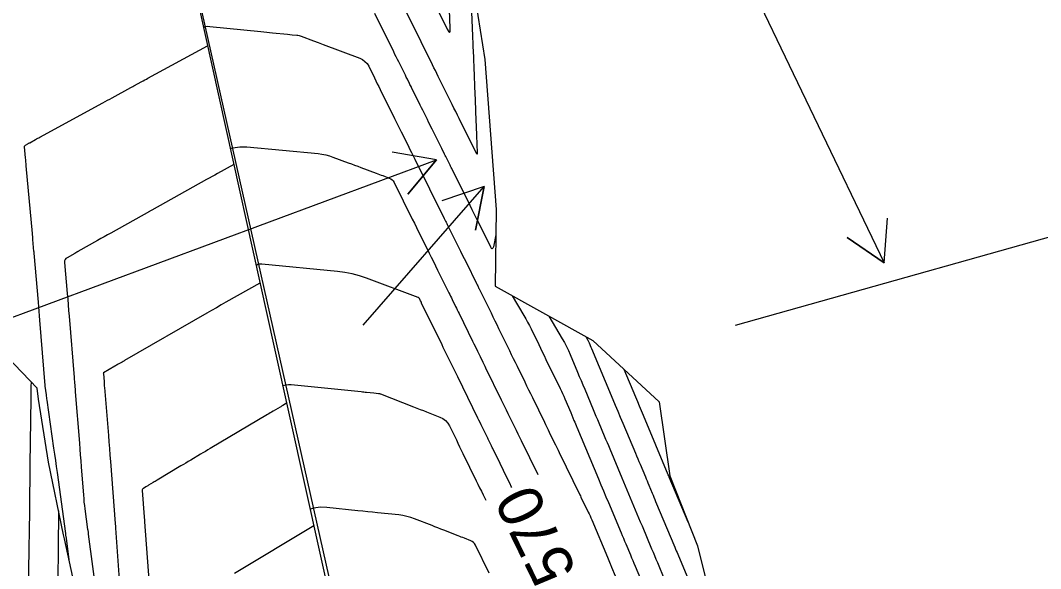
# Model space of a CAD drawing. Extents: x 954385 to 988206, y 1868364 to 1924553.
# Drawn here: x 957911.1 to 958048.1, y 1919236.3 to 1919309.9 of the extents above; entities that cross this region are included whole.
import ezdxf

# ---------------------------------------------------------------- set-up
doc = ezdxf.new("R2010")
doc.units = 0
for name, color, linetype in [('13', 7, 'Continuous'), ('22', 7, 'Continuous'), ('23', 7, 'Continuous'), ('24', 7, 'Continuous'), ('26', 7, 'Continuous'), ('5', 7, 'Continuous'), ('6', 7, 'Continuous'), ('7', 7, 'Continuous'), ('Default', 7, 'Continuous')]:
    doc.layers.add(name, color=color, linetype=linetype)

msp = doc.modelspace()

# ---------------------------------------------------------------- linework, layer by layer
at = {"layer": '13'}
for points in [[(957917.69, 1919237.11), (957917.27, 1919240.31), (957917.26, 1919240.36), (957917.21, 1919240.72), (957917.2, 1919240.78), (957917.2, 1919240.84), (957917.19, 1919240.91), (957917.18, 1919240.97), (957916.06, 1919249.16), (957915.94, 1919249.97), (957915.83, 1919250.78), (957915.72, 1919251.6), (957915.6, 1919252.41), (957914.69, 1919258.86), (957914.66, 1919259.05), (957914.64, 1919259.23), (957914.61, 1919259.42), (957914.58, 1919259.61), (957914.42, 1919260.74), (957914.41, 1919260.8), (957914.41, 1919260.81), (957914.41, 1919260.82), (957914.41, 1919260.83), (957914.41, 1919260.84), (957913.7, 1919269.6), (957913.65, 1919270.2), (957913.6, 1919270.81), (957913.55, 1919271.41), (957913.5, 1919272.02), (957912.93, 1919278.64), (957912.93, 1919278.69), (957912.92, 1919278.75), (957912.92, 1919278.8), (957912.91, 1919278.85), (957912.77, 1919280.44), (957912.75, 1919280.65), (957912.74, 1919280.86), (957912.72, 1919281.07), (957912.7, 1919281.28), (957911.88, 1919290.36), (957911.86, 1919290.63), (957911.83, 1919290.9), (957911.81, 1919291.17), (957911.79, 1919291.44), (957911.66, 1919292.91), (957911.66, 1919292.99), (957911.68, 1919293.05), (957911.72, 1919293.11), (957911.78, 1919293.15), (957912.07, 1919293.31), (957912.14, 1919293.35), (957912.21, 1919293.38), (957912.28, 1919293.42), (957912.35, 1919293.46), (957913.11, 1919293.88), (957913.26, 1919293.96), (957913.41, 1919294.05), (957913.56, 1919294.13), (957913.71, 1919294.21), (957922.16, 1919298.81), (957922.48, 1919298.99), (957922.79, 1919299.16), (957923.11, 1919299.33), (957923.42, 1919299.5), (957925.9, 1919300.87), (957926, 1919300.92), (957926.1, 1919300.97), (957926.2, 1919301.03), (957926.3, 1919301.08), (957927.38, 1919301.66), (957927.59, 1919301.77), (957927.8, 1919301.89), (957928.01, 1919302), (957928.22, 1919302.12), (957936.23, 1919306.49)], [(957939.75, 1919290.51), (957937.56, 1919289.31), (957937.19, 1919289.11), (957936.82, 1919288.91), (957936.46, 1919288.71), (957936.09, 1919288.51), (957928.72, 1919284.39), (957928.67, 1919284.37), (957928.49, 1919284.27), (957928.41, 1919284.22), (957923.25, 1919281.33), (957922.8, 1919281.08), (957922.35, 1919280.83), (957921.9, 1919280.57), (957921.45, 1919280.32), (957918.81, 1919278.84), (957918.78, 1919278.82), (957918.74, 1919278.8), (957918.71, 1919278.78), (957918.67, 1919278.75), (957918.52, 1919278.67), (957918.49, 1919278.65), (957918.45, 1919278.63), (957918.42, 1919278.61), (957918.38, 1919278.59), (957917.35, 1919278.01), (957917.19, 1919277.89), (957917.08, 1919277.75), (957917.03, 1919277.58), (957917.02, 1919277.38), (957917.38, 1919273.2), (957917.44, 1919272.44), (957917.51, 1919271.67), (957917.57, 1919270.9), (957917.63, 1919270.14), (957918.3, 1919261.93), (957918.31, 1919261.77), (957918.32, 1919261.61), (957918.34, 1919261.45), (957918.35, 1919261.29), (957918.43, 1919260.27), (957918.44, 1919260.14), (957918.44, 1919260.08), (957918.45, 1919260.01), (957919.01, 1919253.1), (957919.07, 1919252.31), (957919.13, 1919251.52), (957919.19, 1919250.73), (957919.25, 1919249.94), (957919.55, 1919246.12), (957919.59, 1919245.66), (957919.63, 1919245.19), (957919.68, 1919244.73), (957919.74, 1919244.27), (957920.12, 1919241.52), (957920.13, 1919241.47), (957920.18, 1919241.07), (957920.19, 1919241.02), (957920.2, 1919240.97), (957920.2, 1919240.91), (957920.21, 1919240.86), (957921.26, 1919232.87)], [(957943.26, 1919274.6), (957938.68, 1919272.02), (957938.04, 1919271.66), (957937.41, 1919271.3), (957936.77, 1919270.93), (957936.13, 1919270.57), (957925.09, 1919264.2), (957924.98, 1919264.13), (957924.87, 1919264.07), (957924.76, 1919264), (957924.65, 1919263.94), (957924.2, 1919263.69), (957924.09, 1919263.62), (957923.98, 1919263.56), (957923.87, 1919263.49), (957923.76, 1919263.43), (957922.24, 1919262.55), (957922.23, 1919262.54), (957922.23, 1919262.54), (957922.22, 1919262.54), (957922.23, 1919262.46), (957922.32, 1919261.32), (957922.33, 1919261.13), (957922.35, 1919260.94), (957922.36, 1919260.76), (957922.38, 1919260.57), (957922.9, 1919254.15), (957922.97, 1919253.26), (957923.04, 1919252.38), (957923.11, 1919251.5), (957923.17, 1919250.62), (957923.81, 1919242.33), (957923.81, 1919242.29), (957923.84, 1919241.89), (957923.85, 1919241.83), (957923.85, 1919241.77), (957923.85, 1919241.72), (957923.86, 1919241.66), (957924.48, 1919232.92)], [(957946.83, 1919258.46), (957946.31, 1919258.16), (957946.22, 1919258.11), (957946.14, 1919258.06), (957946.05, 1919258), (957945.96, 1919257.95), (957945.02, 1919257.39), (957944.83, 1919257.28), (957944.64, 1919257.17), (957944.46, 1919257.06), (957944.27, 1919256.95), (957936.59, 1919252.39), (957936.26, 1919252.19), (957935.93, 1919252), (957935.6, 1919251.8), (957935.27, 1919251.61), (957933.96, 1919250.82), (957933.63, 1919250.62), (957933.31, 1919250.43), (957932.98, 1919250.23), (957932.65, 1919250.04), (957929.44, 1919248.13), (957929.31, 1919248.05), (957929.18, 1919247.97), (957929.05, 1919247.89), (957928.91, 1919247.81), (957928.3, 1919247.44), (957928.21, 1919247.39), (957928.12, 1919247.34), (957928.04, 1919247.29), (957927.95, 1919247.23), (957927.6, 1919247.03), (957927.53, 1919246.97), (957927.48, 1919246.9), (957927.45, 1919246.82), (957927.44, 1919246.72), (957927.71, 1919243.2), (957927.72, 1919243.15), (957927.75, 1919242.75), (957927.75, 1919242.69), (957927.75, 1919242.64), (957927.76, 1919242.59), (957927.76, 1919242.54), (957928.36, 1919234.15)], [(957939.85, 1919235.64), (957950.47, 1919242.04)]]:
    msp.add_lwpolyline(points, dxfattribs=at)
at = {"layer": '22'}
msp.add_lwpolyline([(957913.34, 1919260.51), (957905.2, 1919268.95), (957901.47, 1919276.22), (957900.45, 1919278.15), (957895.68, 1919287.34), (957892.38, 1919294.08), (957891.08, 1919296.54), (957886.89, 1919305.86), (957884.81, 1919311.67), (957883.53, 1919315.36), (957879.3, 1919324.66), (957877.21, 1919329.27), (957875.44, 1919333.92), (957871.95, 1919343.39), (957870.15, 1919347.96), (957868.24, 1919352.81), (957864.59, 1919362.24), (957862.78, 1919366.71), (957860.74, 1919371.53), (957856.68, 1919380.86), (957854.25, 1919386.89), (957852.72, 1919390.22), (957848.14, 1919399.44)], dxfattribs=at)
at = {"layer": '23'}
msp.add_lwpolyline([(957937.99, 1919144.23), (957936.12, 1919152.9), (957934.67, 1919159.76), (957934.04, 1919162.68), (957931.82, 1919172.43), (957930.09, 1919179.85), (957929.57, 1919182.18), (957927.35, 1919191.93), (957925.3, 1919200.72), (957925.06, 1919201.66), (957922.64, 1919211.37), (957920.8, 1919221.2), (957920.73, 1919221.63), (957919.01, 1919231), (957917.01, 1919240.26), (957916.9, 1919240.78), (957914.86, 1919250.57), (957913.54, 1919258.99), (957913.34, 1919260.51)], dxfattribs=at)
at = {"layer": '24'}
for points in [[(957910.49, 1919421.74), (957920, 1919379.49), (957928.68, 1919340.64), (957936.81, 1919303.87), (957945.16, 1919266), (957953.4, 1919228.82)], [(957950.26, 1919401.91), (957951.58, 1919391.96), (957954.19, 1919382.29), (957956.96, 1919372.67), (957961.23, 1919363.38), (957964.4, 1919353.84), (957966.1, 1919344.99), (957968.06, 1919334.16), (957970.2, 1919324.39), (957971.9, 1919314.53), (957973.45, 1919304.62), (957974.2, 1919294.54), (957974.99, 1919284.47), (957974.82, 1919274.19), (957987.94, 1919266.88), (957996.88, 1919258.64), (957998.3, 1919248.71), (958002.02, 1919239.29), (958004.43, 1919229.59)], [(957919.01, 1919231), (957917.01, 1919240.26), (957916.9, 1919240.78), (957914.86, 1919250.57), (957913.54, 1919258.99), (957913.34, 1919260.51), (957905.2, 1919268.95)]]:
    msp.add_lwpolyline(points, dxfattribs=at)
at = {"layer": '26'}
for points in [[(958007.13, 1919318.93), (958027.06, 1919277.33), (958022.11, 1919280.72), (958027.06, 1919277.33), (958027.52, 1919283.31)], [(957907.13, 1919268.93), (957966.95, 1919291.17), (957963.12, 1919286.54), (957966.95, 1919291.17), (957961.03, 1919292.17)], [(957957.13, 1919268.93), (957973.35, 1919287.59), (957972.2, 1919281.7), (957973.35, 1919287.59), (957967.67, 1919285.64)], [(958007.13, 1919268.93), (958061.22, 1919284.17), (958057.03, 1919279.87), (958061.22, 1919284.17), (958055.41, 1919285.65)]]:
    msp.add_lwpolyline(points, dxfattribs=at)
at = {"layer": '6'}
for points in [[(957966.83, 1919311.87), (957968.4, 1919308.69), (957968.6, 1919308.36), (957968.73, 1919308.26), (957968.8, 1919308.41), (957968.81, 1919308.8), (957968.71, 1919311.35)], [(957977.06, 1919247.16), (957977.01, 1919247.28), (957976.84, 1919247.62), (957976.67, 1919247.97), (957975.96, 1919249.43), (957975.81, 1919249.73), (957975.66, 1919250.04), (957975.51, 1919250.35), (957975.36, 1919250.66), (957974.59, 1919252.25), (957974.52, 1919252.37), (957974.46, 1919252.5), (957974.4, 1919252.62), (957974.34, 1919252.75), (957974.04, 1919253.37), (957973.91, 1919253.62), (957973.85, 1919253.75), (957973.1, 1919255.28), (957972.96, 1919255.58), (957972.81, 1919255.88), (957972.67, 1919256.18), (957972.52, 1919256.47), (957969.82, 1919262.02), (957969.64, 1919262.38), (957969.47, 1919262.74), (957969.29, 1919263.1), (957969.11, 1919263.46), (957968.41, 1919264.89), (957968.23, 1919265.25), (957968.06, 1919265.61), (957967.88, 1919265.97), (957967.71, 1919266.33), (957964.97, 1919271.92), (957964.96, 1919271.95), (957964.95, 1919271.97), (957964.94, 1919272), (957964.93, 1919272.02), (957964.83, 1919272.22), (957964.68, 1919272.52), (957964.65, 1919272.57), (957964.6, 1919272.62), (957964.56, 1919272.65), (957964.5, 1919272.68), (957957.57, 1919275.26), (957956.62, 1919275.59), (957955.64, 1919275.85), (957954.65, 1919276.04), (957953.65, 1919276.17), (957943.49, 1919277.13), (957943.18, 1919277.16), (957943.14, 1919277.16), (957943.11, 1919277.16), (957943.07, 1919277.15), (957943.04, 1919277.13), (957942.78, 1919276.97), (957942.74, 1919276.95)], [(957987, 1919267.41), (957987.28, 1919266.92), (957987.33, 1919266.84), (957987.38, 1919266.75), (957987.42, 1919266.67), (957987.45, 1919266.58), (957987.69, 1919266.01), (957987.77, 1919265.83), (957990.64, 1919258.98), (957990.97, 1919258.19), (957991.31, 1919257.39), (957991.64, 1919256.59), (957991.98, 1919255.79), (957993.67, 1919251.76), (957993.83, 1919251.38), (957993.98, 1919251.01), (957994.14, 1919250.64), (957994.3, 1919250.26), (957995.01, 1919248.57), (957995.12, 1919248.3), (957995.24, 1919248.02), (957995.35, 1919247.75), (957995.47, 1919247.47), (957995.93, 1919246.38), (957996.04, 1919246.1), (957996.16, 1919245.83), (957996.27, 1919245.55), (957996.39, 1919245.28), (957998.97, 1919239.11), (957999.07, 1919238.88), (957999.16, 1919238.65), (957999.26, 1919238.43), (957999.36, 1919238.2), (958000.13, 1919236.37), (958003.01, 1919229.5)], [(957916.22, 1919244.01), (957916.16, 1919238.96), (957916.16, 1919238.7), (957916.15, 1919238.44), (957916.15, 1919238.18), (957916.15, 1919237.92), (957916.09, 1919233.61)]]:
    msp.add_lwpolyline(points, dxfattribs=at)
at = {"layer": '7'}
for points in [[(957971.55, 1919314.29), (957971.81, 1919307.77), (957971.82, 1919307.42), (957971.84, 1919307.07), (957971.85, 1919306.72), (957971.86, 1919306.37), (957971.92, 1919304.98), (957971.93, 1919304.64), (957971.95, 1919304.29), (957971.96, 1919303.94), (957971.98, 1919303.59), (957972.12, 1919299.94), (957972.14, 1919299.36), (957972.16, 1919298.77), (957972.19, 1919298.19), (957972.21, 1919297.61), (957972.33, 1919294.52), (957972.34, 1919294.32), (957972.34, 1919294.13), (957972.35, 1919293.93), (957972.36, 1919293.74), (957972.4, 1919292.76), (957972.41, 1919292.57), (957972.41, 1919292.39), (957972.43, 1919292.01), (957972.43, 1919291.94), (957972.41, 1919291.91), (957972.39, 1919291.93), (957972.35, 1919291.99), (957970.01, 1919296.71), (957969.78, 1919297.18), (957969.54, 1919297.64), (957969.31, 1919298.11), (957969.08, 1919298.57), (957967.2, 1919302.36), (957967.01, 1919302.75), (957966.82, 1919303.14), (957966.62, 1919303.52), (957966.43, 1919303.91), (957965.66, 1919305.47), (957965.28, 1919306.25), (957964.89, 1919307.02), (957962.39, 1919312.08)], [(957974.93, 1919281.09), (957974.6, 1919279.49), (957974.54, 1919279.29), (957974.46, 1919279.21), (957974.36, 1919279.26), (957974.25, 1919279.44), (957972.68, 1919282.6), (957972.38, 1919283.21), (957972.08, 1919283.82), (957971.77, 1919284.43), (957971.47, 1919285.04), (957969.01, 1919289.98), (957968.94, 1919290.14), (957968.86, 1919290.3), (957968.78, 1919290.46), (957968.7, 1919290.62), (957968.38, 1919291.27), (957968.3, 1919291.43), (957968.22, 1919291.59), (957968.14, 1919291.75), (957968.06, 1919291.91), (957967.67, 1919292.68), (957967.49, 1919293.04), (957967.31, 1919293.4), (957966.38, 1919295.28), (957966.22, 1919295.6), (957966.06, 1919295.92), (957965.9, 1919296.24), (957965.74, 1919296.56), (957965.11, 1919297.84), (957964.95, 1919298.16), (957964.79, 1919298.48), (957964.63, 1919298.8), (957964.47, 1919299.12), (957963.61, 1919300.86), (957963.54, 1919301), (957963.47, 1919301.14), (957963.4, 1919301.28), (957963.33, 1919301.42), (957963.05, 1919301.98), (957962.98, 1919302.12), (957962.91, 1919302.26), (957962.84, 1919302.4), (957962.78, 1919302.54), (957961.9, 1919304.31), (957961.73, 1919304.65), (957961.56, 1919304.99), (957961.39, 1919305.33), (957961.23, 1919305.67), (957958.68, 1919310.82)], [(957935.68, 1919308.98), (957935.68, 1919308.98), (957935.95, 1919309.06), (957936.23, 1919309.1), (957936.52, 1919309.09), (957943.39, 1919308.38), (957943.78, 1919308.34), (957944.16, 1919308.3), (957944.55, 1919308.26), (957944.94, 1919308.23), (957946.97, 1919308.03), (957947.28, 1919308), (957947.59, 1919307.97), (957948.21, 1919307.91), (957948.36, 1919307.89), (957948.51, 1919307.86), (957948.66, 1919307.82), (957948.8, 1919307.77), (957950.45, 1919307.15), (957951.09, 1919306.9), (957951.74, 1919306.66), (957956.66, 1919304.8), (957957.04, 1919304.62), (957957.36, 1919304.38), (957957.64, 1919304.08), (957957.86, 1919303.72), (957958.62, 1919302.16), (957958.82, 1919301.77), (957959.01, 1919301.38), (957959.2, 1919301), (957959.4, 1919300.61), (957961.33, 1919296.72), (957961.55, 1919296.26), (957961.78, 1919295.81), (957962.01, 1919295.35), (957962.23, 1919294.9), (957963.14, 1919293.07), (957963.36, 1919292.62), (957963.59, 1919292.16), (957963.82, 1919291.71), (957964.04, 1919291.25), (957968, 1919283.3), (957968.19, 1919282.91), (957968.24, 1919282.8), (957968.35, 1919282.59), (957968.4, 1919282.48), (957969.93, 1919279.41), (957970.18, 1919278.91), (957970.43, 1919278.4), (957970.68, 1919277.9), (957970.93, 1919277.4), (957972.34, 1919274.55), (957972.43, 1919274.38), (957972.51, 1919274.22), (957972.67, 1919273.89), (957972.71, 1919273.81), (957972.76, 1919273.72), (957972.8, 1919273.64), (957972.84, 1919273.56), (957974.29, 1919270.59), (957974.54, 1919270.07), (957974.8, 1919269.54), (957975.05, 1919269.02), (957975.31, 1919268.5), (957976.76, 1919265.54), (957977.01, 1919265.01), (957977.27, 1919264.49), (957977.53, 1919263.96), (957977.78, 1919263.44), (957978.81, 1919261.33), (957979.07, 1919260.81), (957979.32, 1919260.28), (957979.58, 1919259.76), (957979.84, 1919259.23), (957981.45, 1919255.93), (957981.61, 1919255.59), (957981.78, 1919255.25), (957981.95, 1919254.91), (957982.11, 1919254.57), (957982.78, 1919253.2), (957982.94, 1919252.86), (957983.11, 1919252.52), (957983.28, 1919252.18), (957983.44, 1919251.84), (957986.21, 1919246.17), (957986.29, 1919246.01), (957986.36, 1919245.86), (957987.34, 1919243.85), (957987.47, 1919243.59), (957987.59, 1919243.33), (957987.7, 1919243.07), (957987.82, 1919242.8), (957989.92, 1919237.79), (957990.01, 1919237.57), (957990.1, 1919237.35), (957990.29, 1919236.9), (957990.34, 1919236.79), (957990.38, 1919236.68), (957990.43, 1919236.57), (957990.47, 1919236.46), (957993.42, 1919229.47)], [(957939.27, 1919292.68), (957939.6, 1919292.78), (957940.54, 1919292.92), (957941.51, 1919292.9), (957951.07, 1919291.99), (957951.58, 1919291.92), (957952.09, 1919291.83), (957952.58, 1919291.7), (957953.06, 1919291.53), (957955.12, 1919290.76), (957955.54, 1919290.61), (957955.96, 1919290.45), (957956.38, 1919290.29), (957956.8, 1919290.14), (957958.87, 1919289.36), (957959.09, 1919289.28), (957959.3, 1919289.2), (957959.52, 1919289.12), (957959.74, 1919289.04), (957960.61, 1919288.71), (957960.82, 1919288.62), (957960.99, 1919288.49), (957961.14, 1919288.33), (957961.26, 1919288.13), (957963.7, 1919283.21), (957963.99, 1919282.64), (957964.27, 1919282.07), (957964.55, 1919281.5), (957964.84, 1919280.92), (957965.97, 1919278.64), (957966.26, 1919278.07), (957966.54, 1919277.5), (957966.82, 1919276.93), (957967.11, 1919276.36), (957968.62, 1919273.31), (957968.74, 1919273.08), (957968.85, 1919272.85), (957968.96, 1919272.61), (957969.08, 1919272.38), (957969.53, 1919271.45), (957969.65, 1919271.22), (957969.76, 1919270.99), (957969.87, 1919270.76), (957969.99, 1919270.52), (957971.81, 1919266.8), (957971.98, 1919266.46), (957972.14, 1919266.12), (957972.48, 1919265.44), (957972.56, 1919265.27), (957972.64, 1919265.1), (957972.72, 1919264.93), (957972.81, 1919264.76), (957973.19, 1919263.98), (957973.28, 1919263.8), (957973.37, 1919263.61), (957973.46, 1919263.43), (957973.55, 1919263.24), (957975.66, 1919258.92), (957975.88, 1919258.47), (957976.1, 1919258.01), (957976.32, 1919257.56), (957976.54, 1919257.1), (957977.43, 1919255.28), (957977.65, 1919254.83), (957977.88, 1919254.37), (957978.1, 1919253.92), (957978.32, 1919253.47), (957980.56, 1919248.87)], [(957977.14, 1919272.89), (957978.7, 1919270.25), (957978.95, 1919269.8), (957979.2, 1919269.36), (957979.44, 1919268.9), (957979.67, 1919268.44), (957980.69, 1919266.36), (957980.93, 1919265.86), (957981.17, 1919265.36), (957981.42, 1919264.86), (957981.66, 1919264.36), (957983.58, 1919260.44), (957983.74, 1919260.1), (957983.9, 1919259.76), (957984.05, 1919259.42), (957984.2, 1919259.07), (957984.98, 1919257.2), (957985.12, 1919256.87), (957985.42, 1919256.16), (957985.52, 1919255.91), (957985.7, 1919255.49), (957985.77, 1919255.32), (957985.8, 1919255.24), (957988.71, 1919248.3), (957989.05, 1919247.51), (957989.38, 1919246.71), (957989.72, 1919245.91), (957990.05, 1919245.11), (957991.75, 1919241.06), (957991.9, 1919240.69), (957992.06, 1919240.32), (957992.22, 1919239.95), (957992.37, 1919239.57), (957993, 1919238.09), (957993.15, 1919237.71), (957993.31, 1919237.34), (957993.47, 1919236.97), (957993.62, 1919236.6), (957995.46, 1919232.23)], [(957982.07, 1919270.15), (957983.86, 1919267.11), (957984.15, 1919266.6), (957984.42, 1919266.08), (957984.67, 1919265.55), (957984.91, 1919265.02), (957985.9, 1919262.65), (957986.14, 1919262.07), (957986.38, 1919261.5), (957986.62, 1919260.92), (957986.87, 1919260.35), (957988.01, 1919257.61), (957988.2, 1919257.17), (957988.38, 1919256.73), (957988.57, 1919256.29), (957988.75, 1919255.85), (957989.49, 1919254.09), (957989.67, 1919253.65), (957989.86, 1919253.21), (957990.04, 1919252.77), (957990.23, 1919252.33), (957991.86, 1919248.44), (957992.08, 1919247.9), (957992.31, 1919247.36), (957992.53, 1919246.83), (957992.76, 1919246.29), (957993.66, 1919244.15), (957993.88, 1919243.61), (957994.11, 1919243.07), (957994.33, 1919242.54), (957994.56, 1919242), (957995.85, 1919238.92), (957996.04, 1919238.46), (957996.24, 1919238), (957996.43, 1919237.53), (957996.63, 1919237.07), (957997.6, 1919234.76)], [(958000.76, 1919242.48), (957998.22, 1919248.55), (957998.15, 1919248.7), (957998.09, 1919248.85), (957994.75, 1919256.81), (957994.5, 1919257.43), (957994.24, 1919258.05), (957993.98, 1919258.66), (957993.72, 1919259.28), (957992.16, 1919262.99)], [(957912.19, 1919233), (957912.27, 1919238.97), (957912.27, 1919239.31), (957912.28, 1919239.65), (957912.28, 1919240), (957912.29, 1919240.34), (957912.4, 1919249.54), (957912.4, 1919249.9), (957912.41, 1919249.99), (957912.41, 1919250.22), (957912.53, 1919259.13), (957912.53, 1919259.67), (957912.54, 1919260.21), (957912.55, 1919260.75), (957912.56, 1919261.29), (957912.56, 1919261.31)], [(957946.31, 1919260.8), (957946.4, 1919260.84), (957946.74, 1919260.95), (957947.1, 1919261), (957947.47, 1919260.99), (957956.84, 1919260.02), (957957.02, 1919260.01), (957957.21, 1919259.99), (957957.4, 1919259.97), (957957.58, 1919259.95), (957958.55, 1919259.85), (957958.86, 1919259.81), (957959.16, 1919259.78), (957959.23, 1919259.77), (957959.31, 1919259.76), (957959.38, 1919259.74), (957959.45, 1919259.71), (957963.87, 1919257.99), (957964.31, 1919257.81), (957964.76, 1919257.64), (957965.2, 1919257.47), (957965.64, 1919257.3), (957967.41, 1919256.61), (957967.82, 1919256.4), (957968.18, 1919256.13), (957968.47, 1919255.8), (957968.71, 1919255.41), (957969.63, 1919253.53), (957969.85, 1919253.08), (957970.07, 1919252.62), (957970.29, 1919252.17), (957970.52, 1919251.71), (957972.3, 1919248.05), (957972.53, 1919247.58), (957972.76, 1919247.12), (957972.99, 1919246.65), (957973.21, 1919246.18), (957973.57, 1919245.46)], [(957974.02, 1919235.64), (957972.18, 1919239.42), (957972.07, 1919239.61), (957971.93, 1919239.77), (957971.76, 1919239.9), (957971.56, 1919240), (957970.71, 1919240.33), (957970.5, 1919240.41), (957970.29, 1919240.49), (957970.08, 1919240.58), (957969.87, 1919240.66), (957967.94, 1919241.41), (957967.54, 1919241.57), (957967.15, 1919241.72), (957966.76, 1919241.87), (957966.37, 1919242.03), (957964.03, 1919242.93), (957963.51, 1919243.12), (957962.98, 1919243.27), (957962.44, 1919243.38), (957961.89, 1919243.46), (957959.05, 1919243.75), (957958.39, 1919243.82), (957957.73, 1919243.89), (957957.07, 1919243.96), (957956.41, 1919244.03), (957952.23, 1919244.46), (957951.33, 1919244.49), (957950.47, 1919244.37), (957949.99, 1919244.22)]]:
    msp.add_lwpolyline(points, dxfattribs=at)
at = {"layer": 'Default'}
msp.add_line((958200.6, 1918129.72), (957843.86, 1919719.4), dxfattribs=at)

# ---------------------------------------------------------------- texts
at = {"layer": '5'}
msp.add_text('570', height=6, rotation=116.0131, dxfattribs=at).set_placement((957985.87, 1919235.96))

doc.saveas('drawing.dxf')
